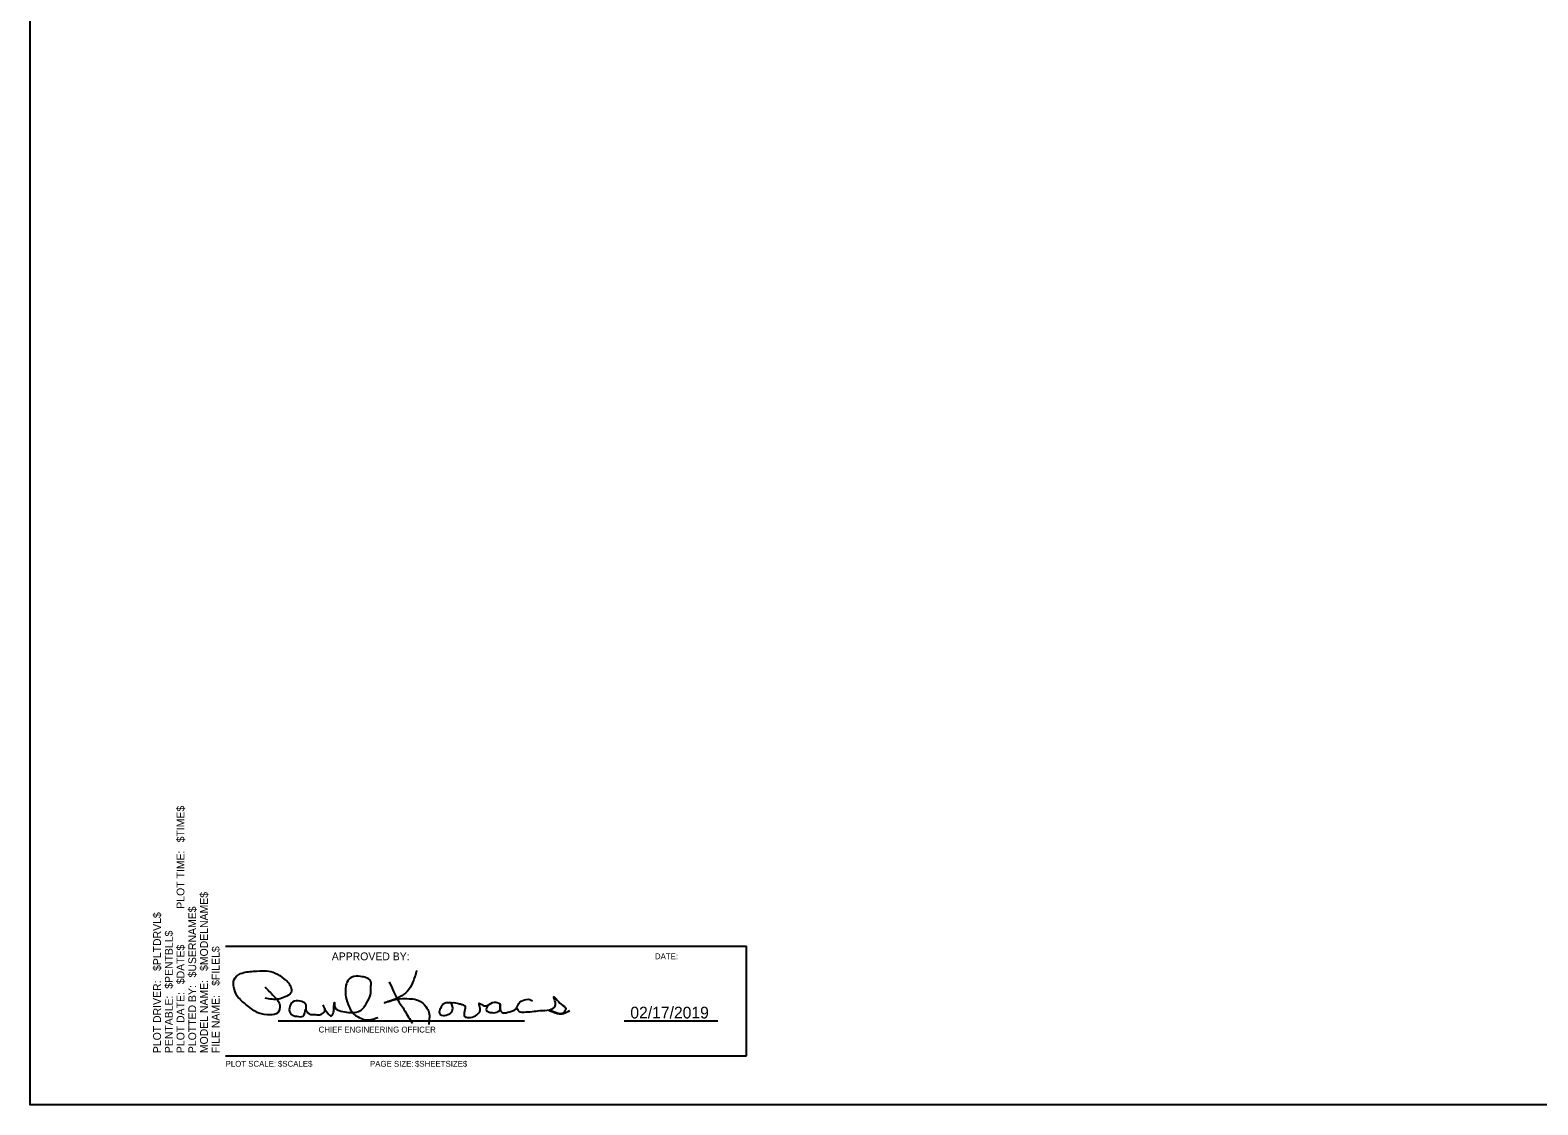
# Model space of a CAD drawing. Extents: x 0 to 2.83, y 0 to 1.83.
# Drawn here: x 0 to 1.286, y 0 to 0.917 of the extents above; entities that cross this region are included whole.
import ezdxf

# ---------------------------------------------------------------- set-up
doc = ezdxf.new("R2010")
doc.units = 0
for name, color, linetype in [('SH_General_Details_Signature-ILTollway', 7, 'Continuous'), ('SH_Printer Plotting Border-ILTollway', 7, 'Continuous'), ('SH_Variables-ILTollway', 7, 'Continuous')]:
    doc.layers.add(name, color=color, linetype=linetype)

msp = doc.modelspace()

# ---------------------------------------------------------------- linework, layer by layer
at = {"layer": 'SH_General_Details_Signature-ILTollway'}
for p, q in [((0.1667, 0.1352), (0.6111, 0.1352)), ((0.6111, 0.0417), (0.6111, 0.1352)), ((0.2117, 0.0717), (0.4217, 0.0717)), ((0.5067, 0.0717), (0.5867, 0.0717)), ((0.1667, 0.0417), (0.6111, 0.0417))]:
    msp.add_line(p, q, dxfattribs=at)
for points in [[(0.2004, 0.1006), (0.2077, 0.0929), (0.2129, 0.085), (0.2112, 0.0785), (0.2047, 0.0768), (0.195, 0.0783), (0.1851, 0.0848), (0.1767, 0.0928), (0.1737, 0.1003), (0.1739, 0.1068), (0.1795, 0.1119), (0.1904, 0.1139), (0.2016, 0.1142), (0.2091, 0.1124), (0.2165, 0.1076), (0.2224, 0.1007), (0.2226, 0.0958), (0.2174, 0.092), (0.212, 0.0902), (0.2004, 0.0909)], [(0.2497, 0.085), (0.2538, 0.0781), (0.257, 0.076), (0.2585, 0.0779), (0.259, 0.0825), (0.2595, 0.0873), (0.2598, 0.0834), (0.2651, 0.08), (0.2715, 0.0789), (0.2802, 0.0796), (0.287, 0.0866), (0.2905, 0.095), (0.2907, 0.1011), (0.2901, 0.1063), (0.2866, 0.1084), (0.2819, 0.1095), (0.2743, 0.109), (0.2702, 0.1043), (0.269, 0.0994), (0.2694, 0.0919), (0.2721, 0.0837), (0.2748, 0.0788), (0.2808, 0.0744), (0.2861, 0.0726), (0.2923, 0.0731), (0.297, 0.0746)], [(0.3298, 0.1147), (0.3262, 0.1041), (0.3216, 0.0967), (0.3153, 0.092), (0.3065, 0.0884), (0.3025, 0.0872), (0.3152, 0.0904), (0.3232, 0.0905), (0.3297, 0.0897), (0.3339, 0.0876), (0.3385, 0.0826), (0.3405, 0.0777), (0.3403, 0.0719), (0.3402, 0.0686)], [(0.3063, 0.1049), (0.31, 0.0967), (0.3134, 0.0898), (0.3196, 0.0802), (0.3227, 0.0749), (0.3261, 0.0696)], [(0.3905, 0.0851), (0.3893, 0.0803), (0.3925, 0.0789), (0.3983, 0.0791), (0.4009, 0.0816), (0.401, 0.0862), (0.4012, 0.0806), (0.4033, 0.0786), (0.4091, 0.0794), (0.4146, 0.0819), (0.4169, 0.0864), (0.4217, 0.0895), (0.4275, 0.0894), (0.4286, 0.0887)], [(0.4152, 0.0824), (0.4171, 0.0796), (0.4214, 0.0791), (0.4283, 0.0796), (0.4348, 0.0804), (0.4431, 0.0811), (0.4475, 0.0836), (0.448, 0.0872), (0.4467, 0.0921), (0.453, 0.0858), (0.4569, 0.0818), (0.4546, 0.0782), (0.4474, 0.0791), (0.4427, 0.0805), (0.4499, 0.078), (0.4549, 0.0779), (0.4604, 0.0804)], [(0.2351, 0.0808), (0.2349, 0.086), (0.2303, 0.0884), (0.2238, 0.0876), (0.2211, 0.0825), (0.2224, 0.0773), (0.2274, 0.0755), (0.2328, 0.0757), (0.2343, 0.0786), (0.2348, 0.0812), (0.2369, 0.0785), (0.2422, 0.0771), (0.2469, 0.0769), (0.2502, 0.0785), (0.2514, 0.0804), (0.2497, 0.085)], [(0.3595, 0.0869), (0.3534, 0.0865), (0.35, 0.0823), (0.3491, 0.0781), (0.3509, 0.0764), (0.3563, 0.077), (0.3593, 0.0788), (0.3602, 0.084), (0.3595, 0.0866), (0.3642, 0.0868), (0.3682, 0.0857), (0.3707, 0.0844), (0.3705, 0.0798), (0.3707, 0.0753), (0.3739, 0.0745), (0.3798, 0.076), (0.3835, 0.0795), (0.3836, 0.0834), (0.383, 0.0866), (0.3862, 0.0849), (0.3902, 0.0848), (0.396, 0.0876), (0.401, 0.0862)]]:
    msp.add_spline(points, degree=3, dxfattribs=at)
at = {"layer": 'SH_Printer Plotting Border-ILTollway'}
msp.add_lwpolyline([(0, 1.8333), (2.8333, 1.8333), (2.8333, 0), (0, 0)], close=True, dxfattribs=at)

# ---------------------------------------------------------------- texts
at = {"layer": 'SH_General_Details_Signature-ILTollway'}
for s, height, p in [('APPROVED BY:', 0.006667, (0.2573, 0.1233)), ('DATE:', 0.005, (0.533, 0.1242)), ('CHIEF ENGINEERING OFFICER', 0.005, (0.2461, 0.0617))]:
    msp.add_text(s, height=height, rotation=0, dxfattribs=at).set_placement(p)
msp.add_text('02/17/2019', height=0.01, dxfattribs=at).set_placement((0.512, 0.0737))
at = {"layer": 'SH_Variables-ILTollway'}
for s, height, rotation, p in [('$TIME$', 0.00667, 90, (0.1316, 0.2239)), ('PLOT TIME:', 0.00667, 90, (0.1316, 0.1673)), ('$MODELNAME$', 0.006667, 90, (0.1516, 0.1142)), ('$USERNAME$', 0.00667, 90, (0.1416, 0.1087)), ('$PLTDRVL$', 0.00667, 90, (0.1116, 0.1142)), ('$PENTBLL$', 0.00667, 90, (0.1216, 0.099)), ('$DATE$', 0.00667, 90, (0.1316, 0.1029)), ('$FILEL$', 0.00667, 90, (0.1616, 0.1015)), ('PLOT DRIVER:', 0.006667, 90, (0.1116, 0.0441)), ('MODEL NAME:', 0.006667, 90, (0.1516, 0.0441)), ('PENTABLE:', 0.00667, 90, (0.1216, 0.0441)), ('PLOT DATE:', 0.00667, 90, (0.1316, 0.0441)), ('PLOTTED BY:', 0.006667, 90, (0.1416, 0.0441)), ('FILE NAME:', 0.00667, 90, (0.1616, 0.0441)), ('PLOT SCALE:', 0.005, 360, (0.1667, 0.0325)), ('$SCALE$', 0.005, 360, (0.2114, 0.0325)), ('PAGE SIZE:', 0.005, 360, (0.2899, 0.0325)), ('$SHEETSIZE$', 0.005, 360, (0.3283, 0.0325))]:
    msp.add_text(s, height=height, rotation=rotation, dxfattribs=at).set_placement(p)

doc.saveas('drawing.dxf')
